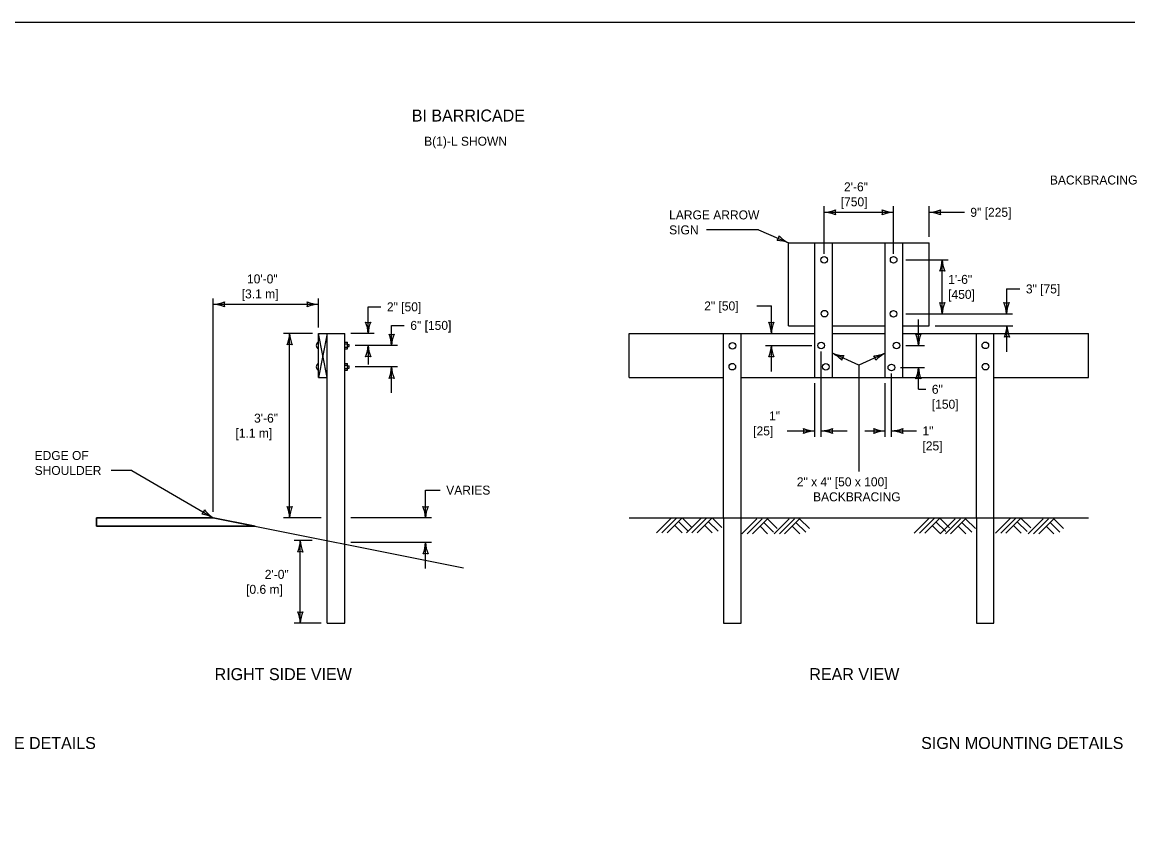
# Model space of a CAD drawing. Extents: x 49991.4 to 50021, y 49987.6 to 50011.4.
# Drawn here: x 50003.93 to 50011.31, y 49993.51 to 49999 of the extents above; entities that cross this region are included whole.
import ezdxf

# ---------------------------------------------------------------- set-up
doc = ezdxf.new("R2010")
doc.units = 0
for name, color, linetype in [('Level 1', 7, 'Continuous'), ('Level 2', 7, 'Continuous'), ('Level 3', 7, 'Continuous'), ('Level 4', 7, 'Continuous')]:
    doc.layers.add(name, color=color, linetype=linetype)

msp = doc.modelspace()

# ---------------------------------------------------------------- linework, layer by layer
at = {"layer": 'Level 1'}
for p, q in [((50009.0441, 49997.5262), (50009.9815, 49997.5262)), ((50009.0441, 49996.9724), (50009.0441, 49997.5262)), ((50009.22, 49996.6277), (50009.22, 49997.5262)), ((50009.3371, 49996.6277), (50009.3371, 49997.5262)), ((50009.6887, 49996.6277), (50009.6887, 49997.5262)), ((50009.8058, 49996.6277), (50009.8058, 49997.5262)), ((50009.9815, 49996.9724), (50009.9815, 49997.5262)), ((50009.0441, 49996.9724), (50009.22, 49996.9724)), ((50009.3371, 49996.9724), (50009.6887, 49996.9724)), ((50009.8058, 49996.9724), (50009.9815, 49996.9724)), ((50005.9089, 49996.6277), (50005.9089, 49996.9206)), ((50005.9677, 49996.6277), (50005.9089, 49996.9206)), ((50005.9677, 49996.9206), (50005.9089, 49996.6277)), ((50005.9089, 49996.9206), (50006.0848, 49996.9206)), ((50005.9677, 49995.5377), (50005.9677, 49996.9206)), ((50006.0848, 49995.5144), (50006.0848, 49996.9206)), ((50007.9809, 49996.9206), (50009.22, 49996.9206)), ((50007.9809, 49996.6277), (50007.9809, 49996.9206)), ((50008.6104, 49995.6901), (50008.6104, 49996.9206)), ((50008.7275, 49995.6901), (50008.7275, 49996.9206)), ((50009.3371, 49996.9206), (50009.6887, 49996.9206)), ((50009.8058, 49996.9206), (50011.0446, 49996.9206)), ((50010.2979, 49995.6901), (50010.2979, 49996.9206)), ((50010.415, 49995.6901), (50010.415, 49996.9206)), ((50011.0446, 49996.6277), (50011.0446, 49996.9206)), ((50006.0848, 49996.8621), (50006.1019, 49996.8621)), ((50006.0848, 49996.8511), (50006.1019, 49996.8511)), ((50006.0848, 49996.8291), (50006.1019, 49996.8291)), ((50006.0848, 49996.8181), (50006.1019, 49996.8181)), ((50006.1019, 49996.8181), (50006.1019, 49996.8621)), ((50006.1019, 49996.8476), (50006.1133, 49996.8476)), ((50006.1019, 49996.8326), (50006.1133, 49996.8326)), ((50006.1133, 49996.8326), (50006.1133, 49996.8476)), ((50006.0848, 49996.719), (50006.102, 49996.719)), ((50006.0848, 49996.708), (50006.102, 49996.708)), ((50006.0848, 49996.686), (50006.102, 49996.686)), ((50006.0848, 49996.675), (50006.102, 49996.675)), ((50006.102, 49996.675), (50006.102, 49996.719)), ((50006.102, 49996.7045), (50006.1134, 49996.7045)), ((50006.102, 49996.6895), (50006.1134, 49996.6895)), ((50006.1134, 49996.6895), (50006.1134, 49996.7045)), ((50005.9089, 49996.6277), (50005.9677, 49996.6277)), ((50007.9809, 49996.6277), (50008.6104, 49996.6277)), ((50008.7275, 49996.6277), (50010.2979, 49996.6277)), ((50010.415, 49996.6277), (50011.0446, 49996.6277)), ((50004.4271, 49995.6339), (50004.4271, 49995.6901)), ((50004.4271, 49995.6901), (50005.2058, 49995.6901)), ((50005.2058, 49995.6901), (50004.4271, 49995.6901)), ((50004.4271, 49995.6901), (50004.4271, 49995.6339)), ((50005.2058, 49995.6901), (50006.8764, 49995.356)), ((50005.4862, 49995.634), (50005.2058, 49995.6901)), ((50007.9809, 49995.6901), (50011.0446, 49995.6901)), ((50008.164, 49995.5901), (50008.264, 49995.6901)), ((50008.199, 49995.5901), (50008.299, 49995.6901)), ((50008.234, 49995.5901), (50008.334, 49995.6901)), ((50008.2845, 49995.6406), (50008.335, 49995.5901)), ((50008.3093, 49995.6654), (50008.3743, 49995.6004)), ((50008.334, 49995.6901), (50008.399, 49995.6251)), ((50008.364, 49995.5901), (50008.464, 49995.6901)), ((50008.399, 49995.5901), (50008.499, 49995.6901)), ((50008.434, 49995.5901), (50008.534, 49995.6901)), ((50008.4845, 49995.6406), (50008.535, 49995.5901)), ((50008.5093, 49995.6654), (50008.5743, 49995.6004)), ((50008.534, 49995.6901), (50008.599, 49995.6251)), ((50008.7338, 49995.5838), (50008.8338, 49995.6838)), ((50008.7688, 49995.5838), (50008.8688, 49995.6838)), ((50008.8038, 49995.5838), (50008.9038, 49995.6838)), ((50008.8791, 49995.6591), (50008.9441, 49995.5941)), ((50008.9038, 49995.6838), (50008.9688, 49995.6188)), ((50008.9485, 49995.5838), (50009.0485, 49995.6838)), ((50008.9835, 49995.5838), (50009.0835, 49995.6838)), ((50009.0185, 49995.5838), (50009.1185, 49995.6838)), ((50009.0938, 49995.6591), (50009.1588, 49995.5941)), ((50009.1185, 49995.6838), (50009.1835, 49995.6188)), ((50009.8826, 49995.5876), (50009.9826, 49995.6876)), ((50009.9176, 49995.5876), (50010.0176, 49995.6876)), ((50009.9526, 49995.5876), (50010.0526, 49995.6876)), ((50010.0031, 49995.6381), (50010.0536, 49995.5876)), ((50010.0279, 49995.6629), (50010.0929, 49995.5979)), ((50010.0526, 49995.6876), (50010.1176, 49995.6226)), ((50010.0559, 49995.5838), (50010.1559, 49995.6838)), ((50010.0909, 49995.5838), (50010.1909, 49995.6838)), ((50010.1259, 49995.5838), (50010.2259, 49995.6838)), ((50010.2012, 49995.6591), (50010.2662, 49995.5941)), ((50010.2259, 49995.6838), (50010.2909, 49995.6188)), ((50010.425, 49995.5876), (50010.525, 49995.6876)), ((50010.46, 49995.5876), (50010.56, 49995.6876)), ((50010.495, 49995.5876), (50010.595, 49995.6876)), ((50010.5455, 49995.6381), (50010.596, 49995.5876)), ((50010.5703, 49995.6629), (50010.6353, 49995.5979)), ((50010.595, 49995.6876), (50010.66, 49995.6226)), ((50010.6434, 49995.5838), (50010.7434, 49995.6838)), ((50010.6784, 49995.5838), (50010.7784, 49995.6838)), ((50010.7134, 49995.5838), (50010.8134, 49995.6838)), ((50010.7887, 49995.6591), (50010.8537, 49995.5941)), ((50010.8134, 49995.6838), (50010.8784, 49995.6188)), ((50005.4862, 49995.6339), (50004.4271, 49995.6339)), ((50004.4271, 49995.6339), (50005.4862, 49995.6339)), ((50005.4862, 49995.6339), (50005.4862, 49995.634)), ((50008.8543, 49995.6343), (50008.9048, 49995.5838)), ((50009.069, 49995.6343), (50009.1195, 49995.5838)), ((50010.1764, 49995.6343), (50010.2269, 49995.5838)), ((50010.7639, 49995.6343), (50010.8144, 49995.5838))]:
    msp.add_line(p, q, dxfattribs=at)
msp.add_lwpolyline([(49999.3835, 49998.9992), (50016.7501, 49998.9992), (50016.7501, 49987.7988), (49999.3835, 49987.7988)], close=True, dxfattribs=at)
for centre in [(50009.2814, 49997.4126), (50009.7456, 49997.412), (50009.2838, 49997.0527), (50009.7438, 49997.0509), (50008.6707, 49996.8382), (50009.262, 49996.8397), (50009.7648, 49996.8409), (50010.3573, 49996.8412), (50008.6694, 49996.6987), (50009.2936, 49996.6976), (50009.7304, 49996.694), (50010.3579, 49996.6987)]:
    msp.add_circle(centre, 0.022, dxfattribs=at)
for centre in [(50005.9186, 49996.8406), (50005.9186, 49996.6976)]:
    msp.add_arc(centre, 0.0243, 113.46993, 246.53007, dxfattribs=at)
at = {"layer": 'Level 3'}
for p, q in [((50009.2814, 49997.4526), (50009.2814, 49997.7694)), ((50009.2814, 49997.7294), (50009.7456, 49997.7294)), ((50009.7456, 49997.452), (50009.7456, 49997.7694)), ((50009.9815, 49997.5662), (50009.9815, 49997.7694)), ((50009.9815, 49997.7294), (50010.2174, 49997.7294)), ((50008.8439, 49997.612), (50008.4966, 49997.612)), ((50008.8439, 49997.612), (50009.0441, 49997.5262)), ((50009.8276, 49997.412), (50010.1094, 49997.412)), ((50010.0694, 49997.0509), (50010.0694, 49997.412)), ((50010.4984, 49997.2179), (50010.4984, 49997.0509)), ((50010.4984, 49997.2179), (50010.5877, 49997.2179)), ((50005.2058, 49995.7301), (50005.2058, 49997.1547)), ((50005.9089, 49997.1147), (50005.2058, 49997.1147)), ((50005.9089, 49996.9606), (50005.9089, 49997.1547)), ((50006.2401, 49996.9206), (50006.2401, 49997.0983)), ((50006.2401, 49997.0983), (50006.3253, 49997.0983)), ((50008.833, 49997.1042), (50008.9299, 49997.1042)), ((50008.9299, 49996.9206), (50008.9299, 49997.1042)), ((50009.8258, 49997.0509), (50010.5384, 49997.0509)), ((50006.3962, 49996.8401), (50006.3962, 49996.9744)), ((50006.3962, 49996.9744), (50006.4814, 49996.9744)), ((50009.9109, 49996.8409), (50009.9109, 49997.0143)), ((50010.0215, 49996.9724), (50010.5413, 49996.9724)), ((50010.5013, 49996.799), (50010.5013, 49996.9724)), ((50005.8689, 49996.9206), (50005.6761, 49996.9206)), ((50005.7161, 49995.6901), (50005.7161, 49996.9206)), ((50006.2801, 49996.9206), (50006.1248, 49996.9206)), ((50006.4362, 49996.8401), (50006.1533, 49996.8401)), ((50006.2401, 49996.8401), (50006.2401, 49996.7143)), ((50008.8899, 49996.8397), (50009.2, 49996.8397)), ((50008.9299, 49996.6663), (50008.9299, 49996.8397)), ((50009.8268, 49996.8409), (50009.9509, 49996.8409)), ((50009.262, 49996.23), (50009.262, 49996.7997)), ((50009.5141, 49996.7081), (50009.3371, 49996.7886)), ((50009.6887, 49996.7886), (50009.5141, 49996.7081)), ((50006.4362, 49996.697), (50006.1534, 49996.697)), ((50006.3962, 49996.5236), (50006.3962, 49996.697)), ((50009.5141, 49996.7081), (50009.5141, 49996.0001)), ((50009.7923, 49996.694), (50009.9509, 49996.694)), ((50009.9109, 49996.5479), (50009.9109, 49996.694)), ((50009.7304, 49996.23), (50009.7304, 49996.654)), ((50009.22, 49996.23), (50009.22, 49996.5877)), ((50009.6887, 49996.23), (50009.6887, 49996.5877)), ((50009.9109, 49996.5479), (50009.9603, 49996.5479)), ((50009.0353, 49996.27), (50009.22, 49996.27)), ((50009.262, 49996.27), (50009.2624, 49996.27)), ((50009.2624, 49996.27), (50009.4354, 49996.27)), ((50009.5541, 49996.27), (50009.6887, 49996.27)), ((50009.7304, 49996.27), (50009.8978, 49996.27)), ((50004.664, 49996.006), (50004.5252, 49996.006)), ((50004.664, 49996.006), (50005.2058, 49995.6901)), ((50006.6226, 49995.6901), (50006.6226, 49995.8747)), ((50006.6226, 49995.8747), (50006.7208, 49995.8747)), ((50005.9277, 49995.6901), (50005.6761, 49995.6901)), ((50006.6626, 49995.6901), (50006.1248, 49995.6901)), ((50005.8677, 49995.5377), (50005.7473, 49995.5377)), ((50005.7873, 49994.987), (50005.7873, 49995.5377)), ((50006.6629, 49995.5244), (50006.1248, 49995.5244)), ((50006.6229, 49995.351), (50006.6229, 49995.5244)), ((50005.9277, 49994.987), (50005.7473, 49994.987))]:
    msp.add_line(p, q, dxfattribs=at)
for centre, radius, start, end in [((50009.27, 49997.9621), 0.233, 272.82731, 292.07716), ((50009.2723, 49997.5073), 0.2223, 67.45601, 87.63952), ((50009.4097, 49997.7294), 0.0548, 162.13882, 197.86118), ((50009.7548, 49997.9515), 0.2223, 247.45601, 267.63952), ((50009.6174, 49997.7294), 0.0548, 342.13882, 17.86118), ((50009.7571, 49997.4967), 0.233, 92.82731, 112.07716), ((50009.97, 49997.9621), 0.233, 272.82731, 292.07716), ((50009.9723, 49997.5073), 0.2223, 67.45601, 87.63952), ((50010.1097, 49997.7294), 0.0548, 162.13882, 197.86118), ((50008.9263, 49997.5767), 0.0548, 318.94023, 354.66259), ((50009.14, 49997.7268), 0.2223, 224.25742, 244.44093), ((50008.963, 49997.3078), 0.233, 69.62872, 88.87857), ((50009.8473, 49997.4212), 0.2223, 337.45601, 357.63952), ((50010.3021, 49997.4235), 0.233, 182.82731, 202.07716), ((50010.0694, 49997.2838), 0.0548, 72.13882, 107.86118), ((50005.1943, 49997.3474), 0.233, 272.82731, 292.07716), ((50005.1966, 49996.8926), 0.2223, 67.45601, 87.63952), ((50005.334, 49997.1147), 0.0548, 162.13882, 197.86118), ((50005.9181, 49997.3368), 0.2223, 247.45601, 267.63952), ((50005.7807, 49997.1147), 0.0548, 342.13882, 17.86118), ((50005.9204, 49996.882), 0.233, 92.82731, 112.07716), ((50010.0694, 49997.1791), 0.0548, 252.13882, 287.86118), ((50009.8367, 49997.0394), 0.233, 2.82731, 22.07716), ((50010.2915, 49997.0418), 0.2223, 157.45601, 177.63952), ((50010.4984, 49997.1791), 0.0548, 252.13882, 287.86118), ((50010.2657, 49997.0394), 0.233, 2.82731, 22.07716), ((50010.7205, 49997.0418), 0.2223, 157.45601, 177.63952), ((50006.2401, 49997.0488), 0.0548, 252.13882, 287.86118), ((50006.0074, 49996.9091), 0.233, 2.82731, 22.07716), ((50006.4622, 49996.9114), 0.2223, 157.45601, 177.63952), ((50008.9299, 49997.0488), 0.0548, 252.13882, 287.86118), ((50008.6972, 49996.9091), 0.233, 2.82731, 22.07716), ((50009.152, 49996.9114), 0.2223, 157.45601, 177.63952), ((50010.2792, 49996.9816), 0.2223, 337.45601, 357.63952), ((50010.734, 49996.9839), 0.233, 182.82731, 202.07716), ((50005.494, 49996.9298), 0.2223, 337.45601, 357.63952), ((50005.9488, 49996.9321), 0.233, 182.82731, 202.07716), ((50006.3962, 49996.9683), 0.0548, 252.13882, 287.86118), ((50006.1635, 49996.8286), 0.233, 2.82731, 22.07716), ((50006.6183, 49996.8309), 0.2223, 157.45601, 177.63952), ((50009.9109, 49996.9691), 0.0548, 252.13882, 287.86118), ((50009.6782, 49996.8294), 0.233, 2.82731, 22.07716), ((50010.1331, 49996.8317), 0.2223, 157.45601, 177.63952), ((50010.5013, 49996.8442), 0.0548, 72.13882, 107.86118), ((50005.7161, 49996.7924), 0.0548, 72.13882, 107.86118), ((50006.018, 49996.8493), 0.2223, 337.45601, 357.63952), ((50006.4728, 49996.8516), 0.233, 182.82731, 202.07716), ((50008.7078, 49996.8489), 0.2223, 337.45601, 357.63952), ((50009.1626, 49996.8512), 0.233, 182.82731, 202.07716), ((50006.2401, 49996.7119), 0.0548, 72.13882, 107.86118), ((50008.9299, 49996.7115), 0.0548, 72.13882, 107.86118), ((50009.2368, 49996.5902), 0.2223, 42.99986, 63.18337), ((50009.423, 49997.0052), 0.233, 248.37116, 267.62101), ((50009.4538, 49996.7355), 0.0548, 137.68267, 173.40503), ((50009.604, 49996.9942), 0.2223, 272.20826, 292.39176), ((50009.5723, 49996.7349), 0.0548, 6.89106, 42.61342), ((50009.7966, 49996.5821), 0.233, 117.57956, 136.82941), ((50006.1741, 49996.7062), 0.2223, 337.45601, 357.63952), ((50006.6289, 49996.7085), 0.233, 182.82731, 202.07716), ((50009.6888, 49996.7032), 0.2223, 337.45601, 357.63952), ((50010.1437, 49996.7055), 0.233, 182.82731, 202.07716), ((50006.3962, 49996.5688), 0.0548, 72.13882, 107.86118), ((50009.9109, 49996.5658), 0.0548, 72.13882, 107.86118), ((50009.2292, 49996.4921), 0.2223, 247.45601, 267.63952), ((50009.0918, 49996.27), 0.0548, 342.13882, 17.86118), ((50009.2315, 49996.0373), 0.233, 92.82731, 112.07716), ((50009.2505, 49996.5027), 0.233, 272.82731, 292.07716), ((50009.2528, 49996.0479), 0.2223, 67.45601, 87.63952), ((50009.3902, 49996.27), 0.0548, 162.13882, 197.86118), ((50009.6979, 49996.4921), 0.2223, 247.45601, 267.63952), ((50009.5605, 49996.27), 0.0548, 342.13882, 17.86118), ((50009.7002, 49996.0373), 0.233, 92.82731, 112.07716), ((50009.7189, 49996.5027), 0.233, 272.82731, 292.07716), ((50009.7212, 49996.0479), 0.2223, 67.45601, 87.63952), ((50009.8586, 49996.27), 0.0548, 162.13882, 197.86118), ((50005.095, 49995.7547), 0.0548, 311.89357, 347.61594), ((50005.0985, 49995.4833), 0.233, 62.58207, 81.83192), ((50005.3256, 49995.8774), 0.2223, 217.21077, 237.39427), ((50005.7161, 49995.8183), 0.0548, 252.13882, 287.86118), ((50005.4834, 49995.6786), 0.233, 2.82731, 22.07716), ((50005.9382, 49995.6809), 0.2223, 157.45601, 177.63952), ((50006.6226, 49995.8183), 0.0548, 252.13882, 287.86118), ((50006.3899, 49995.6786), 0.233, 2.82731, 22.07716), ((50006.8447, 49995.6809), 0.2223, 157.45601, 177.63952), ((50005.5652, 49995.5469), 0.2223, 337.45601, 357.63952), ((50006.02, 49995.5492), 0.233, 182.82731, 202.07716), ((50006.4008, 49995.5336), 0.2223, 337.45601, 357.63952), ((50006.8556, 49995.5359), 0.233, 182.82731, 202.07716), ((50005.7873, 49995.4095), 0.0548, 72.13882, 107.86118), ((50006.6229, 49995.3962), 0.0548, 72.13882, 107.86118), ((50005.7873, 49995.1152), 0.0548, 252.13882, 287.86118), ((50005.5546, 49994.9755), 0.233, 2.82731, 22.07716), ((50006.0094, 49994.9778), 0.2223, 157.45601, 177.63952)]:
    msp.add_arc(centre, radius, start, end, dxfattribs=at)
at = {"layer": 'Level 4'}
for p, q in [((50008.6104, 49995.6901), (50008.6104, 49994.987)), ((50008.7275, 49994.987), (50008.7275, 49995.6901)), ((50010.2979, 49995.6901), (50010.2979, 49994.987)), ((50010.415, 49994.987), (50010.415, 49995.6901)), ((50005.9677, 49994.987), (50005.9677, 49995.5377)), ((50006.0848, 49994.987), (50006.0848, 49995.5144)), ((50005.9677, 49994.987), (50006.0848, 49994.987)), ((50008.6104, 49994.987), (50008.7275, 49994.987)), ((50010.2979, 49994.987), (50010.415, 49994.987))]:
    msp.add_line(p, q, dxfattribs=at)

# ---------------------------------------------------------------- texts
at = {"layer": 'Level 2'}
for s, height, p in [('BI BARRICADE', 0.08, (50006.5312, 49998.3355)), ('B(1)-L SHOWN', 0.06, (50006.6138, 49998.1739)), ('2\'-6"', 0.06, (50009.4144, 49997.8694)), ('BACKBRACING', 0.06, (50010.7878, 49997.915)), ('[750]', 0.06, (50009.3926, 49997.7694)), ('LARGE ARROW', 0.06, (50008.2479, 49997.682)), ('9" [225]', 0.06, (50010.2574, 49997.6994)), ('SIGN', 0.06, (50008.2479, 49997.582)), ('10\'-0"', 0.06, (50005.4319, 49997.2547)), ('1\'-6"', 0.06, (50010.1094, 49997.2515)), ('[3.1 m]', 0.06, (50005.3967, 49997.1547)), ('[450]', 0.06, (50010.1094, 49997.1515)), ('3" [75]', 0.06, (50010.6277, 49997.1879)), ('2" [50]', 0.06, (50006.3653, 49997.0683)), ('2" [50]', 0.06, (50008.4819, 49997.0742)), ('6" [150]', 0.06, (50006.5214, 49996.9444)), ('6" ', 0.06, (50010.0003, 49996.5179)), ('[150]', 0.06, (50010.0003, 49996.4179)), ('3\'-6"', 0.06, (50005.4792, 49996.3253)), ('1" ', 0.06, (50008.9146, 49996.34)), ('[25]', 0.06, (50008.8087, 49996.24)), ('[1.1 m]', 0.06, (50005.3547, 49996.2254)), ('1" ', 0.06, (50009.9378, 49996.24)), ('[25]', 0.06, (50009.9378, 49996.14)), ('EDGE OF', 0.06, (50004.0149, 49996.076)), ('SHOULDER', 0.06, (50004.0149, 49995.976)), ('2" x 4" [50 x 100]', 0.06, (50009.0997, 49995.9001)), ('VARIES', 0.06, (50006.7608, 49995.8447)), ('BACKBRACING', 0.06, (50009.208, 49995.8001)), ('2\'-0"', 0.06, (50005.5504, 49995.2824)), ('[0.6 m]', 0.06, (50005.4259, 49995.1824)), ('RIGHT SIDE VIEW', 0.08, (50005.2159, 49994.6062)), ('REAR VIEW', 0.08, (50009.1831, 49994.6062)), ('BARRICADE DETAILS', 0.08, (50003.324, 49994.1466)), ('SIGN MOUNTING DETAILS', 0.08, (50009.9291, 49994.1466))]:
    msp.add_text(s, height=height, dxfattribs=at).set_placement(p)

doc.saveas('drawing.dxf')
